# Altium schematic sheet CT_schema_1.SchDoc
size 458 x 210 mm
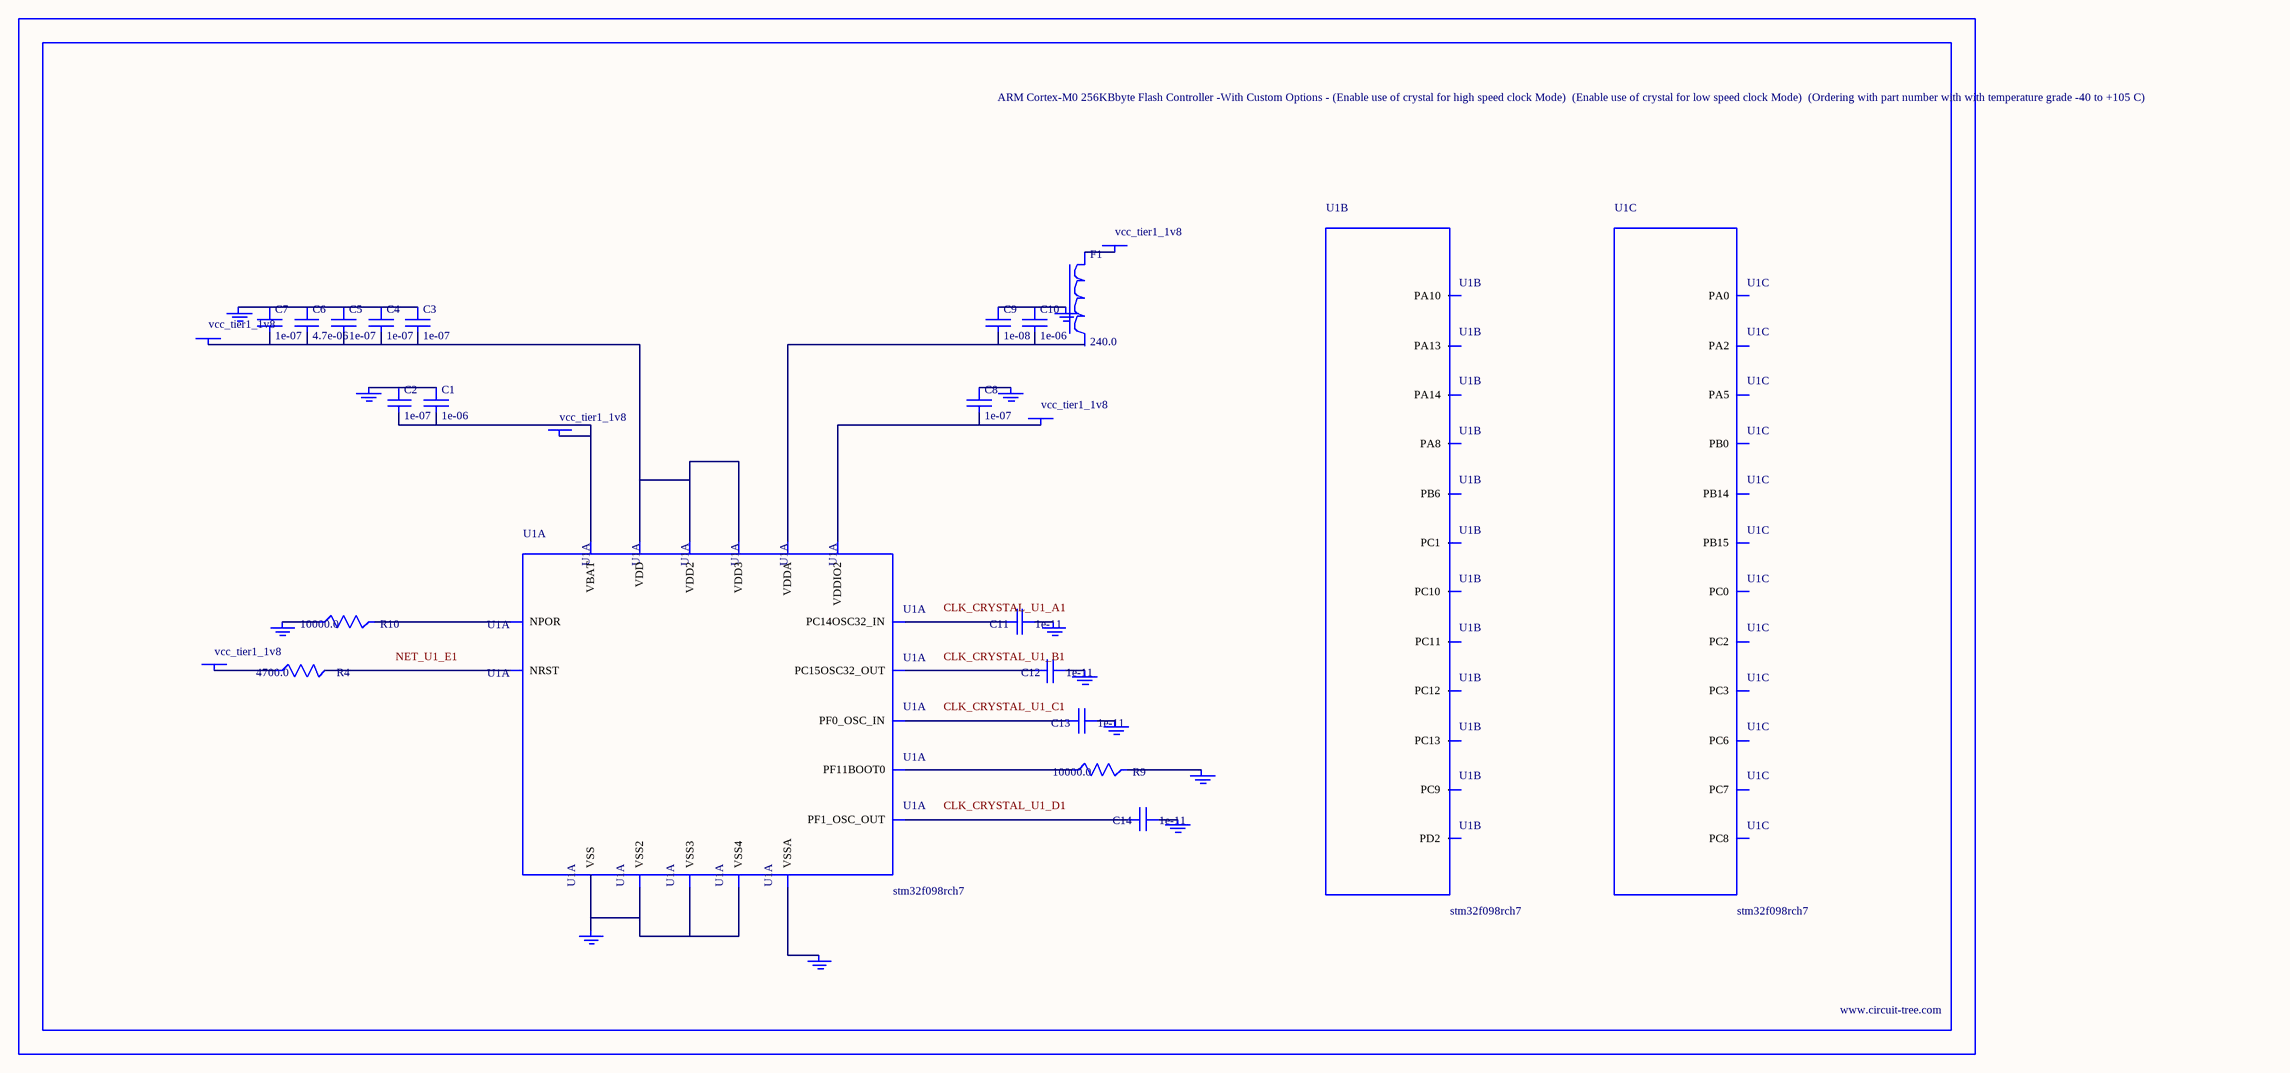
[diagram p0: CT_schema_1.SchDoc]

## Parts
BORDER0  (no value)
C1  1e-06  [C0603]
C2  1e-07  [C0603]
C3  1e-07  [C0603]
C4  1e-07  [C0603]
C5  1e-07  [C0603]
C6  4.7e-06  [C0603]
C7  1e-07  [C0603]
C8  1e-07  [C0603]
C9  1e-08  [C0603]
C10  1e-06  [C0603]
C11  1e-11  [C0402]
C12  1e-11  [C0402]
C13  1e-11  [C0402]
C14  1e-11  [C0402]
F1  240.0  [L0603]
GND_INSTANCE_0_0  (no value)
GND_INSTANCE_0_1  (no value)
GND_INSTANCE_0_2  (no value)
GND_INSTANCE_0_3  (no value)
GND_INSTANCE_0_4  (no value)
GND_INSTANCE_0_5  (no value)
GND_INSTANCE_0_6  (no value)
GND_INSTANCE_0_7  (no value)
GND_INSTANCE_0_8  (no value)
GND_INSTANCE_0_9  (no value)
GND_INSTANCE_0_10  (no value)
GND_INSTANCE_0_11  (no value)
POWER_INSTANCE_0_0  vcc_tier1_1v8
POWER_INSTANCE_0_1  vcc_tier1_1v8
POWER_INSTANCE_0_2  vcc_tier1_1v8
POWER_INSTANCE_0_3  vcc_tier1_1v8
POWER_INSTANCE_0_4  vcc_tier1_1v8
R4  4700.0  [R0603]
R9  10000.0  [R0603]
R10  10000.0  [R0603]
U1  stm32f098rch7  [UFBGA64]  (parts A,B,C of 6)

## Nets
NetC1_1: C1.1 C2.1 GND_INSTANCE_0_0.0(GND)
NetC1_2: C1.2 C2.2 POWER_INSTANCE_0_0.0(PWR) U1.B2(VBAT)
NetC3_1: C3.1 C4.1 C5.1 C6.1 C7.1 GND_INSTANCE_0_2.0(GND)
NetC3_2: C3.2 C4.2 C5.2 C6.2 C7.2 POWER_INSTANCE_0_2.0(PWR) U1.D2(VDD) U1.E4(VDD2) U1.E5(VDD3)
NetC8_1: C8.1 GND_INSTANCE_0_3.0(GND)
NetC8_2: C8.2 POWER_INSTANCE_0_3.0(PWR) U1.E6(VDDIO2)
NetC9_1: C9.1 C10.1 GND_INSTANCE_0_1.0(GND)
NetC9_2: C9.2 C10.2 U1.H1(VDDA)
NetC11_1: C11.1 GND_INSTANCE_0_6.0(GND)
NetC11_2: C11.2 U1.A1(PC14OSC32_IN)
NetC12_1: C12.1 GND_INSTANCE_0_7.0(GND)
NetC12_2: C12.2 U1.B1(PC15OSC32_OUT)
NetC13_1: C13.1 GND_INSTANCE_0_8.0(GND)
NetC13_2: C13.2 U1.C1(PF0_OSC_IN)
NetC14_1: C14.1 GND_INSTANCE_0_9.0(GND)
NetC14_2: C14.2 U1.D1(PF1_OSC_OUT)
NetF1_1: F1.1 POWER_INSTANCE_0_1.0(PWR)
NetGND_INSTANCE_0_4_0: GND_INSTANCE_0_4.0(GND) R9.2
NetGND_INSTANCE_0_5_0: GND_INSTANCE_0_5.0(GND) R10.1
NetGND_INSTANCE_0_10_0: GND_INSTANCE_0_10.0(GND) U1.F1(VSSA)
NetGND_INSTANCE_0_11_0: GND_INSTANCE_0_11.0(GND) U1.C2(VSS) U1.D4(VSS2) U1.D5(VSS3) U1.D6(VSS4)
NetPOWER_INSTANCE_0_4_0: POWER_INSTANCE_0_4.0(PWR) R4.1
NetR4_2: R4.2 U1.E1(NRST)
NetR9_1: R9.1 U1.B4(PF11BOOT0)
NetR10_2: R10.2 U1.G6(NPOR)

Not connected (* = marked no-connect by the designer): F1 2; U1 A2(PC13) A7(PA14) A8(PA13) B5(PD2) B6(PC11) B7(PC10) C5(PC12) C6(PA10) D3(PB6) D7(PA8) D8(PC9) E2(PC1) E3(PC0) E7(PC7) E8(PC8) F2(PC2) F3(PA2) F4(PA5) F5(PB0) F6(PC6) F7(PB15) F8(PB14) G1(PC3) G2(PA0)

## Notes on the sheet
- Labels drawn without touching a wire or pin: CLK_CRYSTAL_U1_A1, CLK_CRYSTAL_U1_B1, CLK_CRYSTAL_U1_C1, CLK_CRYSTAL_U1_D1, NET_U1_E1

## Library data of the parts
BORDER0 = BORDER_PAGE0
C1 C10 = C0603C105K3RACTU
C2-C5 C7 C8 = 06035C104K4Z2A
C6 = GRM188R6YA475KE15D
C9 = 06035C103K4Z2A
C11-C14 = C0402C100K3GACTU
F1 = Z0603C241ASMST
GND_INSTANCE_0_0-GND_INSTANCE_0_11 = GND
POWER_INSTANCE_0_0-POWER_INSTANCE_0_4 = PWR
R4 = RC0603JR-074K7L
R9 R10 = RC0603JR-0710KL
